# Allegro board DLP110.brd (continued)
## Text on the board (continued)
User.39: DATE: AUG 2023 | PAC NUMBER: 305-PD-23-0762 | JOB NAME: 2511801A_6802_V20 | FILM LAYER: | REV: 1 | PACTRON | 3000 PATRICK HENRY Dr, SANTA CLARA, CA 95054. | 408 329 5500 (phone), 408 747 1239 (fax).
User.40: STACKUP: 8 LAYERS | TOTAL THICKNESS: 63mils +/-10% | DIELECTRIC (5.840 mils) | DIELECTRIC (6.000 mils) | DIELECTRIC (8.260 mils) | DIELECTRIC (4.000 mils) | TOP (0.5 OZ + PLATING) | 02_GND1 (2 OZ) | 03_SIG1 (1 OZ) | 04_GND2 (2 OZ) | 05_SIG2 (1 OZ) | 06_PWR (2 OZ) | 07_GND3 (2 OZ) | BOTTOM (0.5 OZ + PLATING) | FR370HR
User.41: FIGURE | SIZE | 11.811 | 12.0 | 40.0 | 51.181 | 157.0 | DRILL CHART: TOP to BOTTOM | ALL UNITS ARE IN MILS | TOLERANCE | +3.0/-3.0 | +2.0/-2.0 | +2.0/-0.0 | PLATED | NON-PLATED | QTY | 18 | 562 | 22 | 4 | 3 | 2
